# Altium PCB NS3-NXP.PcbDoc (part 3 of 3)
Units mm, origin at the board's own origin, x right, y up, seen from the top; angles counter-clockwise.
Board outline 147 x 83 mm, 2 copper layers (Top Layer, Bottom Layer); 303 components, 312 nets, 1163 pads, 118 vias.
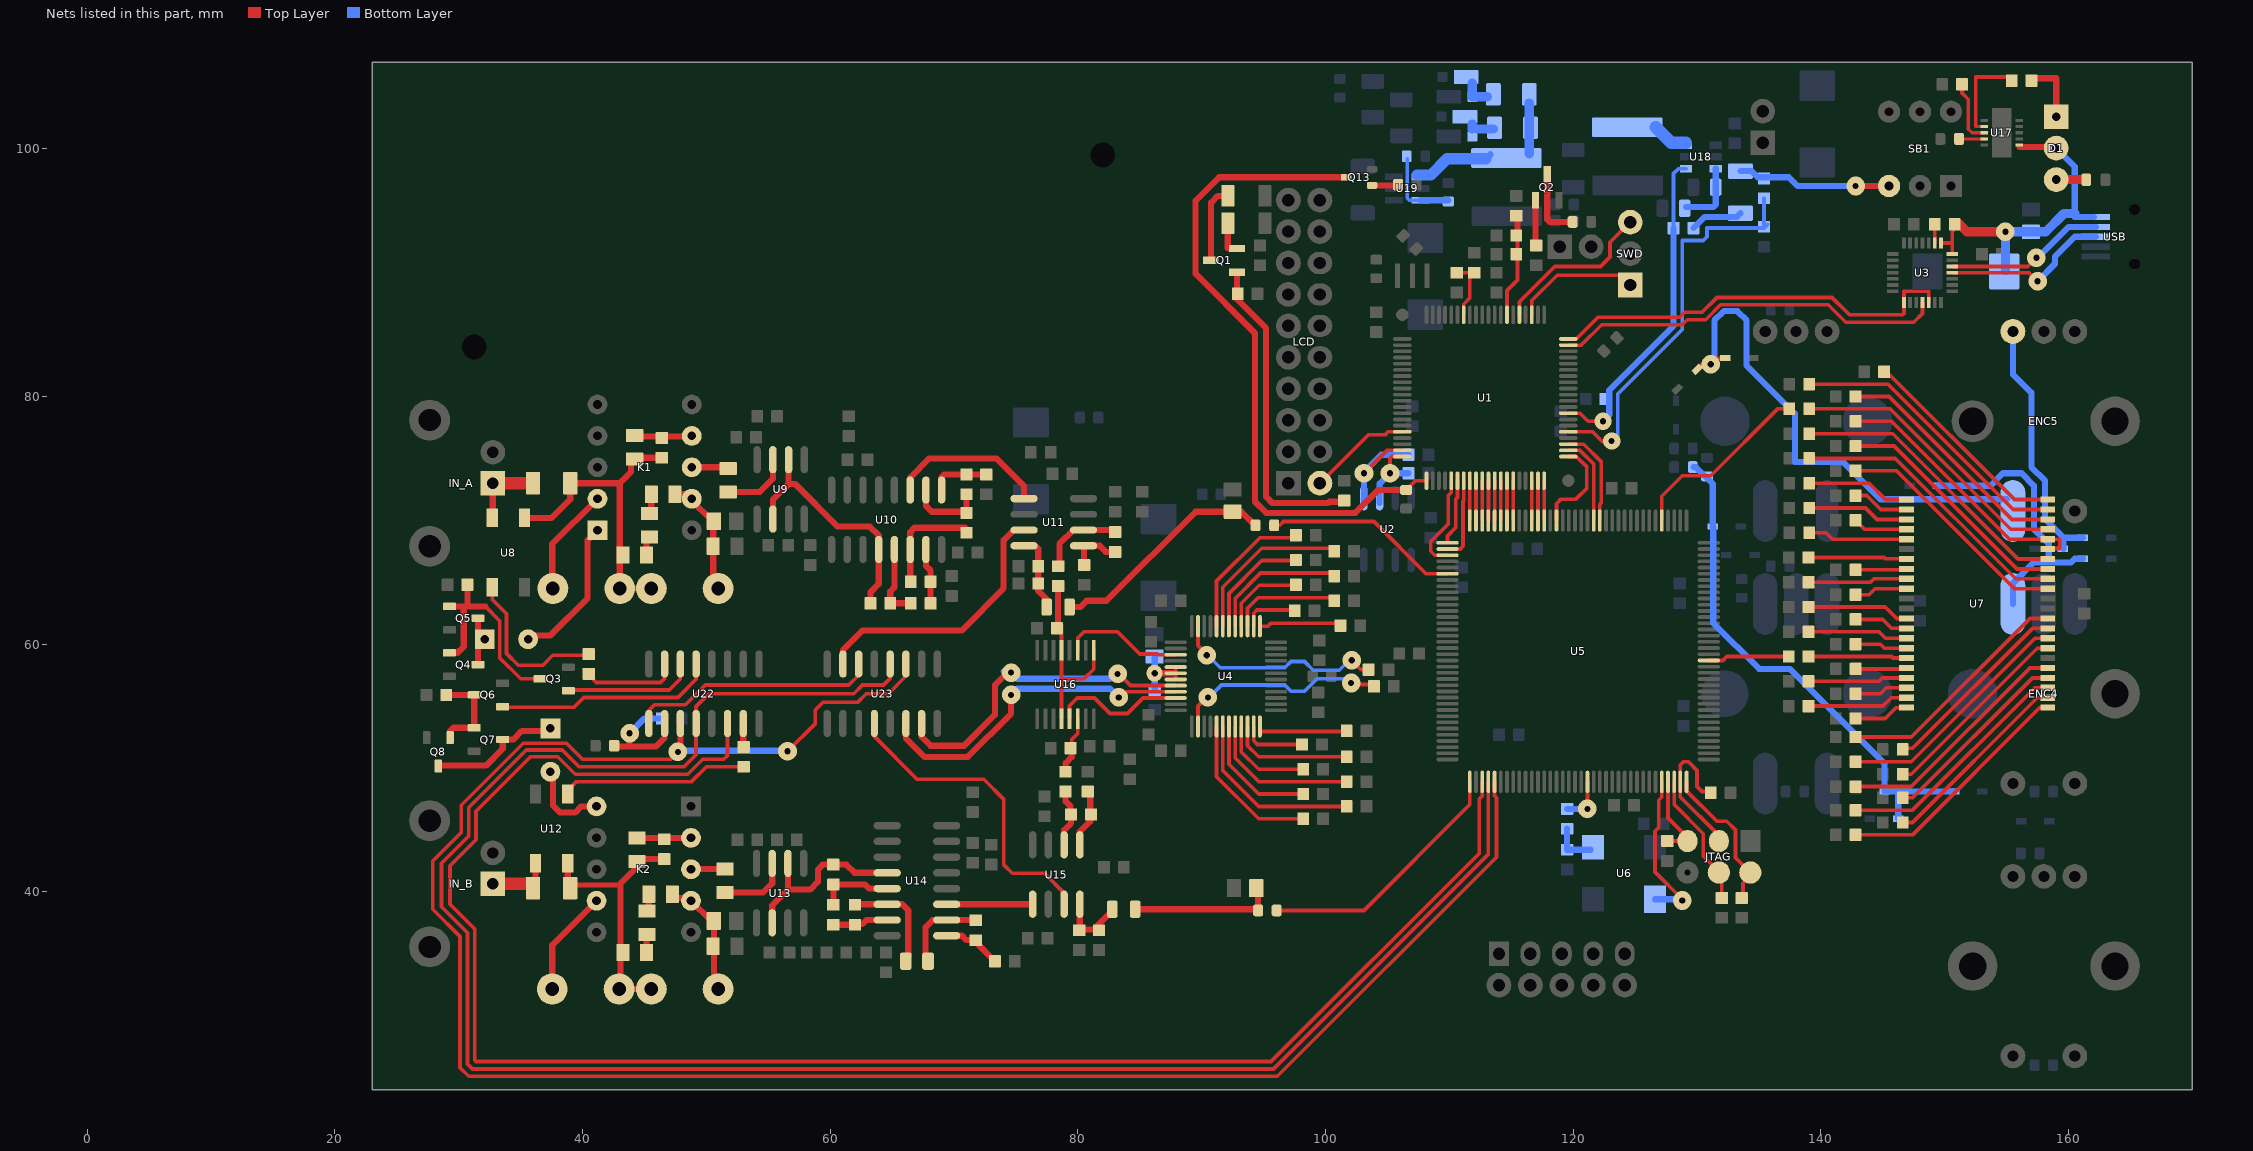
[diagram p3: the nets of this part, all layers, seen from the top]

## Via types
v1: diameter 1.5, hole 0.5, Top Layer to Bottom Layer, 93 vias
v2: diameter 1.6, hole 0.5, Top Layer to Bottom Layer, 18 vias
v3: diameter 1.4, hole 0.5, Top Layer to Bottom Layer, 4 vias
v4: diameter 1.2, hole 0.5, Top Layer to Bottom Layer, 2 vias
v5: diameter 1.3, hole 0.5, Top Layer to Bottom Layer, 1 vias

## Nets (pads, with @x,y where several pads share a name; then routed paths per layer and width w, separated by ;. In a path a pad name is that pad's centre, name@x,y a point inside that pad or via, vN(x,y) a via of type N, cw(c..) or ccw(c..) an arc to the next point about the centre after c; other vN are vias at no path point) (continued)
NetC14_1: C14.1 C15.2 U4.5 U4.6 U4.7 | length 5.4
  Top Layer w0.3: U4.7@87.898,57.154 U4.6@87.898,57.654 U4.5@87.898,58.154
  Top Layer w0.5: v5(86.2,57.65) U4.6@87.894,57.65
  Bottom Layer w0.5: C14.1@86.2,56.3 v5(86.2,57.65) C15.2@86.2,59
NetC40_1: C40.1 IN_A.1 U8.4 | length 6
  Top Layer w0.5: U8.4@32.75,70.25 IN_A.1@32.75,73
  Top Layer w1: IN_A.1@32.75,73 C40.1@36,73
NetC40_2: C40.2 C41.2 C43.1 C44.1 R89.2 R93.1 U8.3 | length 25.5
  Top Layer w0.5: U8.3@35.3,70.2 37.5,70.2 39,71.7 C40.2@39,73 43,73 ; C41.2@45.55,64.5 C43.1@43,64.5 43,73 ; C44.1@46.4,75.05 44.05,75.05 43.9,74.9 43.9,73.9 43,73
NetC41_1: C41.1 C42.2 K1.9 R91.1 R92.2 | length 9.6
  Top Layer w0.5: R91.1@47.45,72.1 48.46,72.1 K1.9@48.82,71.74 ; K1.9@48.75,71.68 50.55,69.88 50.55,64.9 C41.1@50.95,64.5
NetC43_2: C43.2 K1.2 | length 8.7
  Top Layer w0.5: C43.2@37.55,64.5 37.55,68.1 K1.2@41.13,71.68
NetC44_2: C44.2 K1.7 R93.2 | length 4.8
  Top Layer w0.5: R93.2@43.94,76.76 K1.7@48.75,76.76
NetC49_2: C49.2 R103.2 R104.1 U11.4 | length 6.2
  Top Layer w0.5: U11.4@75.65,67.945 76.555,67.945 76.8,67.7 R103.2@76.8,66.3 C49.2@76.8,64.9 76.8,64.3 77.475,63.625 R104.1@77.475,63
NetC50_2: C50.2 R104.2 R105.1 | length 18.6
  Top Layer w0.5: R104.2@79.325,63 80.2,63 80.7,63.5 82.3,63.5 89.5,70.7 C50.2@92.5,70.7 93.2,70.7 R105.1@94.3,69.6
NetC53_2: C53.2 R106.2 U16.1 U16.5 U16.12 | length 15.4
  Top Layer w0.3: C53.2@78.3,61.3 78.3,61.5 C53.2@78.4,61.6 ; U16.12@78.675,53.975 78.675,57.2 ; C53.2@78.675,61.5 U16.5@78.675,59.525 78.675,57.2 ; U16.1@81.275,59.525 81.275,57.975 80.5,57.2 78.675,57.2
  Top Layer w0.5: C53.2@78.4,61.6 R106.2@78.4,64.7
NetC54_1: C54.1 Q4.3 Q5.3 | length 3.6
  Top Layer w0.5: Q4.3@31.55,58.35 Q5.3@31.55,62
NetC54_2: C54.2 K1.1 | length 12.1
  Top Layer w0.5: C54.2@35.6,60.4 35.6,60.5 35.8,60.7 37.4,60.7 40.4,63.7 40.4,68.4 K1.1@41.2,69.2
NetC55_1: C55.1 IN_B.1 U12.3 | length 4.9
  Top Layer w0.5: C55.1@36,40.65 36.2,40.85 U12.3@36.2,42.2
  Top Layer w1: IN_B.1@32.75,40.65 C55.1@36,40.65
NetC55_2: C55.2 C56.2 C58.1 C59.1 R110.2 R113.1 U12.4 | length 21.5
  Top Layer w0.4: C55.2@39.1,40.55 43.05,40.55
  Top Layer w0.5: U12.4@38.8,42.2 38.8,40.85 C55.2@39.1,40.55 ; 43.05,40.55 43.05,32.25 C58.1@42.95,32.15 C56.2@45.55,32.15 ; 43.05,40.65 44.25,41.85 44.25,42.45 44.45,42.65 C59.1@46.6,42.65
NetC56_1: C56.1 C57.2 K2.4 R112.1 R127.2 | length 9.7
  Top Layer w0.5: R112.1@47.35,39.5 48.53,39.5 K2.4@48.75,39.28 50.38,37.65 C57.2@50.6,37.65 50.6,32.5 C56.1@50.95,32.15
NetC58_2: C58.2 K2.7 | length 8.6
  Top Layer w0.5: C58.2@37.55,32.15 37.55,35.7 K2.7@41.13,39.28
NetC59_2: C59.2 K2.2 R113.2 | length 4.5
  Top Layer w0.5: R113.2@44.26,44.36 K2.2@48.75,44.36
NetC64_2: C64.2 R123.2 R124.1 U15.4 | length 5.5
  Top Layer w0.5: U15.4@80.155,39 80.155,36.955 81.645,36.955 81.645,37.345 R124.1@82.775,38.475
NetC65_2: C65.2 R124.2 R125.1 | length 11.7
  Top Layer w0.5: R124.2@84.625,38.6 R125.1@94.45,38.6 ; C65.2@94.4,40.3 94.55,40.15 R125.1@94.55,38.5
NetC68_2: C68.2 R126.2 U16.14 | length 4.7
  Top Layer w0.3: 79.5,50.9 79.5,52.3 79.975,52.775 U16.14@79.975,53.975
  Top Layer w0.5: R126.2@79,49.7 79,50.4 79.5,50.9
NetC69_1: C69.1 Q7.3 Q8.3 | length 10.6
  Top Layer w0.5: Q8.3@28.35,50.2 32.2,50.2 33.55,51.55 Q7.3@33.55,52.3 34.4,52.3 35.1,53 C69.1@37.4,53
NetC69_2: C69.2 K2.10 | length 6.7
  Top Layer w0.5: C69.2@37.4,49.5 37.6,49.3 37.6,47 38.2,46.4 39.4,46.4 39.9,46.9 K2.10@41.13,46.9
  Bottom Layer w0.5: K2.10@41,46.9 K2.10@41.13,46.9
NetC71_2: C71.2 R107.1 U22.10 | length 9.6
  Top Layer w0.5: C71.2@42.609,51.741 43.8,51.741 ; v1(43.8,52.8) 43.8,51.741 ; U22.10@46.625,53.6 46.625,52.425 45.941,51.741 43.8,51.741
  Bottom Layer w0.5: v1(43.8,52.8) 45,54 R107.1@46.4,54
NetC84_2: C84.2 R132.1 R133.2 U1.7 | length 8.3
  Top Layer w0.3: U1.7@114.65,86.6 114.65,88.55 115.5,89.4 C84.2@115.5,93
  Top Layer w0.5: C84.2@115.5,93 R132.1@115.5,94.5
NetC88_1: C88.1 C89.1 L2.2 U19.1 | length 10.7
  Bottom Layer w0.55: L2.2@112.95,99.2 L2.2@113.3,99.55
  Bottom Layer w0.75: L2.2@116.45,99.6 116.45,101.6 C89.1@116.45,103.7
  Bottom Layer w0.9: U19.1@107.4,97.9 108.5,97.9 109.8,99.2 L2.2@112.95,99.2
NetC88_2: C88.2 D18.A D19.C | length 1.7
  Bottom Layer w0.75: 111.85,101.6 111.85,102 ; 112.25,101.6 C88.2@113.55,101.6
NetC89_2: C89.2 D20.A D21.C | length 2.3
  Bottom Layer w0.75: D21.C@111.85,105.3 D20.A@111.85,104.2 C89.2@113.05,104.2
NetC117_1: C117.1 D5.A D7.A D9.A D11.A R151.1 | length 41.9
  Bottom Layer w0.5: R151.1@129.7,74.3 129.9,74.3 131.26,72.94 D7.A@131.26,69.5 ; D7.A@131.3,69.46 131.3,61.7 135,58 137.5,58 145.14,50.36 D9.A@145.14,48.1 D11.A@150.76,48.1 ; D5.A@146.24,45.9 146.24,48.06
NetD1_1: D1.1 R130.2 | length 4.8
  Top Layer w0.5: R130.2@157.3,105.7 159,105.7 D1.1@159,102.6
NetD1_3: D1.3 R129.2 | length 2.4
  Top Layer w0.75: D1.3@159,97.52 R129.2@161.405,97.52
NetD2_A: D2.A R135.2 SB1.3 | length 13.1
  Top Layer w0.5: v1(142.8,97) SB1.3@145.5,97
  Bottom Layer w0.5: D2.A@133.5,98.2 134.4,98.2 134.9,97.7 137.4,97.7 138.1,97 143.1,97 v1@143.1,96.8 ; SB1.3@145.4,97.1 SB1.3@145.5,97
NetD2_C: D2.C R137.1 | length 4.3
  Bottom Layer w0.5: R137.1@129.7,93.6 130.6,94.5 133.2,94.5 D2.C@133.5,94.8
NetD12_C: D12.C D13.C ENC4.1 | length 23.4
  Bottom Layer w0.5: D13.C@149.44,72.8 153.7,72.8 154.7,73.8 156.2,73.8 157.2,72.8 157.2,69.3 158.4,68.1 158.4,66.6 ; ENC4.1@155.5,63.25 155.5,64.9 157.2,66.6 158.4,66.6 ; D12.C@161.16,66.9 160.5,66.9 160.2,66.6 158.4,66.6
NetD14_C: D14.C D15.C ENC5.1 | length 20.8
  Bottom Layer w0.5: ENC5.1@155.5,85.25 155.5,81.8 157,80.3 157,74.3 158.1,73.2 158.1,70.1 159.6,68.6 ; D15.C@159.6,67.7 159.6,68.6 ; D14.C@161.16,68.6 159.6,68.6
NetD16_C: D16.C D17.C ENC5.4 | length 40.9
  Top Layer w0.3: D16.C@130.006,82.206 130.4,82.6 v1(131.1,82.6) 131.6,83.1 D17.C@132.26,83.1
  Bottom Layer w0.5: v1(131.1,82.6) 131.4,82.9 131.4,86.138 132.162,86.9 133.238,86.9 134,86.138 134,82.5 137.9,78.6 137.9,74.7 141.8,74.7 144.8,71.7 ENC5.4@155,71.7
NetK1_8: K1.8 R94.1 | length 2.9
  Top Layer w0.5: K1.8@48.82,74.28 R94.1@51.67,74.28
NetK2_3: K2.3 R114.1 | length 2.7
  Top Layer w0.5: K2.3@48.78,41.85 R114.1@51.5,41.85
NetL1_1: L1.1 U18.3 | length 3
  Bottom Layer w1: L1.1@126.65,101.75 127.9,100.5 U18.3@129.1,100.5
NetQ1_1: Q1.1 R6.1 R7.1 | length 25.7
  Top Layer w0.5: Q1.1@92.85,90.05 92.85,87.85 95.2,85.5 95.2,71.9 95.7,71.4 100.2,71.4 100.3,71.5 R7.1@101.5,71.5
NetQ1_2: Q1.2 R8.2 | length 2.8
  Top Layer w0.5: R8.2@92.1,94 92.1,92 92.15,91.95 Q1.2@92.85,91.95
NetQ1_3: Q1.3 R3.2 | length 6.2
  Top Layer w0.5: Q1.3@90.75,91 90.75,95.65 91.3,96.2 R3.2@92.1,96.2
NetQ2_1: Q2.1 R14.2 | length 3.6
  Top Layer w0.5: R14.2@116.95,92.25 Q2.1@116.95,95.85
NetQ2_3: Q2.3 R15.1 | length 5.8
  Top Layer w0.5: Q2.3@117.9,97.95 117.9,94.3 118.1,94.1 R15.1@119.95,94.1
NetQ3_3: Q3.3 Q4.1 Q5.1 R108.2 | length 17.1
  Top Layer w0.3: 32.15,63.05 33.3,61.9 33.3,58.9 35,57.2 Q3.3@36.6,57.2
  Top Layer w0.5: Q5.1@29.25,63.05 30.4,63.05 ; 29.9,59.3 30.4,59.8 30.4,63.05 ; 30.7,63.15 R108.2@30.7,64.8 ; 32.15,63.05 30.4,63.05
NetQ6_3: Q6.3 Q7.1 Q8.1 R128.2 | length 7.5
  Top Layer w0.5: R128.2@29,55.9 Q6.3@31.25,55.9 Q7.1@31.25,53.25 29.55,53.25 29.3,53 Q8.1@29.3,52.45
NetQ13_1: Q13.1 R2.1 | length 2
  Top Layer w0.5: Q13.1@103.75,97.05 R2.1@105.8,97.05
NetR19_2: R19.2 U3.9 | length 1.5
  Top Layer w0.3: U3.9@149.2,92.4 R19.2@149.2,93.9
NetR20_2: R20.2 U4.47 | length 17.3
  Top Layer w0.3: U4.47@89.698,61.454 89.698,59.902 90.4,59.2 v1(90.4,59.1) ; v1(102.114,58.698) 102.87,57.942 R20.2@103.474,57.942
  Bottom Layer w0.3: v1(90.4,59.1) 90.5,59.1 91.5,58.1 96.7,58.1 97.2,58.6 98.3,58.6 99,57.9 101.1,57.9 101.898,58.698 v1(102.114,58.698)
NetR21_2: R21.2 U4.14 | length 17.4
  Top Layer w0.3: U4.14@89.698,53.354 89.698,54.998 90.5,55.8 v1(90.5,55.7) ; v1@102.061,56.75 R21.2@103.842,56.75
  Bottom Layer w0.3: v1(90.5,55.7) 90.6,55.7 91.6,56.7 96.7,56.7 97.2,56.2 98.3,56.2 99.3,57.2 101.523,57.2 101.762,56.962 101.961,56.962 v1(102.061,56.862)
NetR22_1: R22.1 U4.37 | length 6.6
  Top Layer w0.3: U4.37@94.698,61.454 95.354,61.454 95.6,61.7 100.9,61.7 R22.1@101.1,61.5
NetR23_1: R23.1 U4.38 | length 4.5
  Top Layer w0.3: U4.38@94.198,61.454 94.198,62.498 94.452,62.752 R23.1@97.5,62.752
NetR24_1: R24.1 U4.39 | length 8.9
  Top Layer w0.3: U4.39@93.698,61.454 93.698,62.898 94.55,63.75 100.45,63.75 R24.1@100.7,63.5
NetR25_1: R25.1 U4.40 | length 6.8
  Top Layer w0.3: U4.40@93.198,61.454 93.198,63.298 94.65,64.75 R25.1@97.6,64.75
NetR26_1: R26.1 U4.41 | length 11.2
  Top Layer w0.3: U4.41@92.698,61.454 92.698,63.698 94.75,65.75 100.45,65.75 R26.1@100.7,65.5
NetR27_1: R27.1 U4.42 | length 9.1
  Top Layer w0.3: U4.42@92.198,61.454 92.198,64.098 94.85,66.75 R27.1@97.6,66.75
NetR28_1: R28.1 U4.43 | length 13.6
  Top Layer w0.3: U4.43@91.698,61.454 91.698,64.598 94.85,67.75 100.45,67.75 R28.1@100.7,67.5
NetR29_1: R29.1 U4.44 | length 11.7
  Top Layer w0.3: U4.44@91.198,61.454 91.198,65.098 94.7,68.6 97.55,68.6 R29.1@97.7,68.75
NetR30_1: R30.1 U4.24 | length 7
  Top Layer w0.3: U4.24@94.698,52.954 R30.1@101.7,52.954
NetR31_1: R31.1 U4.23 | length 4.8
  Top Layer w0.3: U4.23@94.198,53.354 94.198,52.202 94.5,51.9 R31.1@97.76,51.9
NetR32_1: R32.1 U4.22 | length 9.9
  Top Layer w0.3: U4.22@93.698,53.354 93.698,51.802 94.6,50.9 R32.1@101.7,50.9
NetR33_1: R33.1 U4.21 | length 7.6
  Top Layer w0.3: U4.21@93.198,53.354 93.198,51.302 94.6,49.9 R33.1@98.2,49.9
NetR34_1: R34.1 U4.20 | length 12.3
  Top Layer w0.3: U4.20@92.698,53.354 92.698,50.802 94.6,48.9 R34.1@101.7,48.9
NetR35_1: R35.1 U4.19 | length 10
  Top Layer w0.3: U4.19@92.198,53.354 92.198,50.302 94.6,47.9 R35.1@98.2,47.9
NetR36_1: R36.1 U4.18 | length 14.8
  Top Layer w0.3: U4.18@91.698,53.354 91.698,49.802 94.6,46.9 R36.1@101.7,46.9
NetR37_1: R37.1 U4.17 | length 12.5
  Top Layer w0.3: U4.17@91.198,53.354 91.198,49.302 94.6,45.9 R37.1@98.2,45.9
NetR38_1: R38.1 R80.1 U6.3 | length 3.6
  Bottom Layer w0.5: R38.1@119.5,45.1 R80.1@119.5,43.4 U6.3@121.4,43.4
NetR38_2: R38.2 U5.20 | length 3.8
  Top Layer w0.3: v1(121.146,46.7) U5.20@121.146,48.886
  Bottom Layer w0.5: R38.2@119.5,46.7 v1(121.146,46.7)
NetR39_2: R39.2 U7.7 | length 8
  Top Layer w0.3: R39.2@139,67 145.1,67 145.2,66.9 146.892,66.9 U7.7@146.916,66.876
NetR40_2: R40.2 U7.8 | length 4
  Top Layer w0.3: R40.2@142.8,66 U7.8@146.84,66
NetR41_2: R41.2 U7.9 | length 8.1
  Top Layer w0.3: R41.2@138.9,65 144,65 144.276,65.276 U7.9@146.916,65.276
NetR42_2: R42.2 U7.10 | length 4.3
  Top Layer w0.3: R42.2@142.8,64 143.9,64 144.376,64.476 U7.10@146.916,64.476
NetR43_2: R43.2 U7.13 | length 8.3
  Top Layer w0.3: R43.2@139,63 145.2,63 146.124,62.076 U7.13@146.916,62.076
NetR44_2: R44.2 U7.14 | length 4.4
  Top Layer w0.3: R44.2@142.8,62 145,62 145.724,61.276 U7.14@146.916,61.276
NetR45_2: R45.2 U7.15 | length 8.1
  Top Layer w0.3: R45.2@139,61 144.7,61 145.224,60.476 U7.15@146.916,60.476
NetR46_2: R46.2 U7.16 | length 4.3
  Top Layer w0.3: R46.2@142.8,60 144.8,60 145.124,59.676 U7.16@146.916,59.676
NetR47_2: R47.2 U7.29 | length 15.9
  Top Layer w0.3: R47.2@146.6,49.5 147.3,49.5 157.476,59.676 U7.29@158.316,59.676
NetR48_2: R48.2 U7.30 | length 19.6
  Top Layer w0.3: R48.2@142.8,50.5 147.3,50.5 157.276,60.476 U7.30@158.316,60.476
NetR49_2: R49.2 U7.31 | length 15.7
  Top Layer w0.3: R49.2@146.6,51.6 147.4,51.6 157.076,61.276 U7.31@158.316,61.276
NetR50_2: R50.2 U7.32 | length 19.5
  Top Layer w0.3: R50.2@142.8,52.5 147.3,52.5 156.876,62.076 U7.32@158.316,62.076
NetR51_2: R51.2 U7.35 | length 19.5
  Top Layer w0.3: R51.2@142.8,74 146.1,74 155.624,64.476 U7.35@158.316,64.476
NetR52_2: R52.2 U7.36 | length 23.3
  Top Layer w0.3: R52.2@139.05,75 146,75 155.724,65.276 U7.36@158.316,65.276
NetR53_2: R53.2 U7.37 | length 19.6
  Top Layer w0.3: R53.2@142.8,76 145.9,76 155.824,66.076 U7.37@158.316,66.076
NetR54_2: R54.2 U7.38 | length 23.5
  Top Layer w0.3: R54.2@139.05,77 145.8,77 155.924,66.876 U7.38@158.316,66.876
NetR55_1: R55.1 U7.1 | length 8.4
  Top Layer w0.3: R55.1@139.05,73 143.9,73 145.224,71.676 U7.1@146.916,71.676
NetR56_1: R56.1 U7.2 | length 4.6
  Top Layer w0.3: R56.1@142.8,72 143.7,72 144.824,70.876 U7.2@146.916,70.876
NetR57_1: R57.1 U7.3 | length 8.2
  Top Layer w0.3: R57.1@139.05,71 143.6,71 144.524,70.076 U7.3@146.916,70.076
NetR58_1: R58.1 U7.4 | length 4.4
  Top Layer w0.3: R58.1@142.8,70 143.524,69.276 U7.4@146.916,69.276
NetR59_1: R59.1 U7.5 | length 8.1
  Top Layer w0.3: R59.1@139.05,69 140.4,69 140.924,68.476 U7.5@146.916,68.476
NetR60_1: R60.1 U7.18 | length 4
  Top Layer w0.3: R60.1@142.8,58 U7.18@146.84,58
NetR61_1: R61.1 U7.19 | length 8
  Top Layer w0.3: R61.1@139,57 144.7,57 144.976,57.276 U7.19@146.916,57.276
NetR62_1: R62.1 U7.20 | length 4.3
  Top Layer w0.3: R62.1@142.8,56 144.8,56 145.276,56.476 U7.20@146.916,56.476
NetR63_1: R63.1 U7.21 | length 8.2
  Top Layer w0.3: R63.1@139,55 145,55 145.676,55.676 U7.21@146.916,55.676
NetR64_1: R64.1 U7.22 | length 4.5
  Top Layer w0.3: R64.1@142.8,54 145.2,54 146.076,54.876 U7.22@146.916,54.876
NetR65_1: R65.1 U7.23 | length 19.8
  Top Layer w0.3: R65.1@142.8,44.6 147.4,44.6 157.676,54.876 U7.23@158.316,54.876
NetR66_1: R66.1 U7.24 | length 15.9
  Top Layer w0.3: R66.1@146.6,45.6 147.4,45.6 157.476,55.676 U7.24@158.316,55.676
NetR67_1: R67.1 U7.25 | length 19.6
  Top Layer w0.3: R67.1@142.8,46.6 147.4,46.6 157.276,56.476 U7.25@158.316,56.476
NetR68_1: R68.1 U7.26 | length 15.7
  Top Layer w0.3: R68.1@146.6,47.6 147.4,47.6 157.076,57.276 U7.26@158.316,57.276
NetR69_1: R69.1 U7.27 | length 19.5
  Top Layer w0.3: R69.1@142.8,48.5 147.3,48.5 156.876,58.076 U7.27@158.316,58.076
NetR70_1: R70.1 U7.42 | length 19.6
  Top Layer w0.3: R70.1@142.8,80 145.5,80 155.424,70.076 U7.42@158.316,70.076
NetR71_1: R71.1 U7.43 | length 23.5
  Top Layer w0.3: R71.1@139.05,81 145.4,81 155.524,70.876 U7.43@158.316,70.876
NetR72_1: R72.1 U7.44 | length 17.5
  Top Layer w0.3: R72.1@145.1,82 145.3,82 155.624,71.676 U7.44@158.316,71.676
NetR73_1: R73.1 U7.17 | length 8
  Top Layer w0.3: R73.1@139,59 145.7,59 145.824,58.876 U7.17@146.916,58.876
NetR74_1: R74.1 U7.41 | length 23.3
  Top Layer w0.3: R74.1@139.05,79 145.6,79 155.324,69.276 U7.41@158.316,69.276
NetR75_1: R75.1 U7.39 U7.40 | length 22.2
  Top Layer w0.3: R75.1@142.8,78 145.7,78 155.224,68.476 U7.40@158.316,68.476 159.276,68.476 159.276,67.724 158.364,67.724 U7.39@158.316,67.676
NetR88_2: R88.2 U8.1 | length 13.2
  Top Layer w0.3: U8.1@32.7,64.6 32.7,63.6 33.85,62.45 33.85,59.25 34.8,58.3 36.8,58.3 37.6,59.1 40.4,59.1 R88.2@40.5,59.2
NetR89_1: R89.1 R90.2 | length 1.2
  Top Layer w0.5: R89.1@45.15,67.2 R90.2@45.15,68.4
NetR90_1: R90.1 R91.2 | length 1.4
  Top Layer w0.5: R90.1@45.55,70.7 R91.2@45.55,72.1
NetR94_2: R94.2 U9.3 | length 5.6
  Top Layer w0.5: R94.2@51.75,72.3 54.3,72.3 55.365,73.365 U9.3@55.365,74.9
NetR95_1: R95.1 R96.2 U10.13 | length 6.1
  Top Layer w0.5: U10.13@65.185,67.65 65.185,64.585 64.85,64.25 R95.1@64.85,63.3 R96.2@66.5,63.3
NetR95_2: R95.2 U9.2 U9.6 U10.12 | length 20.1
  Top Layer w0.5: U9.6@55.365,70.1 55.365,71.665 56.635,72.935 ; U9.2@56.635,74.9 56.635,72.935 ; R95.2@63.25,63.3 63.25,64.2 63.915,64.865 U10.12@63.915,67.65 63.915,68.785 63.2,69.5 60.6,69.5 57.165,72.935 56.635,72.935
NetR96_1: R96.1 R97.2 U10.15 | length 4.5
  Top Layer w0.5: U10.15@67.725,67.65 67.725,66.325 68.1,65.95 R97.2@68.1,65.05 R96.1@68.1,63.3
NetR97_1: R97.1 R98.2 U10.14 | length 8.8
  Top Layer w0.5: R97.1@66.5,65.05 66.455,65.095 U10.14@66.455,67.65 66.455,69.055 66.8,69.4 70.9,69.4 R98.2@71,69.3
NetR98_1: R98.1 R99.2 U10.2 | length 5.9
  Top Layer w0.5: U10.2@67.725,72.45 67.725,71.175 68.2,70.7 R98.1@70.9,70.7 ; R98.1@71,70.8 R99.2@71,72.1
NetR99_1: R99.1 R100.2 U10.1 | length 4.7
  Top Layer w0.5: U10.1@68.995,72.45 68.995,73.495 69.2,73.7 R99.1@71,73.7 R100.2@72.6,73.7
NetR101_2: R101.2 R102.1 U11.5 | length 4.3
  Top Layer w0.5: U11.5@80.45,67.945 81.755,67.945 82.25,67.45 R102.1@83,67.45 ; R101.2@80.5,66.4 U11.5@80.5,67.895
NetR102_2: R102.2 R106.1 U11.6 | length 6.6
  Top Layer w0.5: R106.1@78.5,66.3 78.5,68.1 79.615,69.215 U11.6@80.45,69.215 R102.2@82.835,69.215
NetR105_2: R105.2 U5.114 | length 15.8
  Top Layer w0.3: R105.2@95.9,69.6 96.3,69.6 96.6,69.9 103.9,69.9 108.114,65.686 U5.114@109.846,65.686
NetR109_2: R109.2 U12.1 | length 14.8
  Top Layer w0.3: U12.1@39.1,48.3 39.1,48.5 39.5,48.9 48.8,48.9 50,50.1 R109.2@53,50.1
NetR110_1: R110.1 R111.2 | length 1.4
  Top Layer w0.5: R110.1@45.15,35.1 R111.2@45.15,36.5
NetR111_1: R111.1 R112.2 | length 1.2
  Top Layer w0.5: R111.1@45.35,38.6 R112.2@45.35,39.8
NetR114_2: R114.2 U13.3 | length 5.5
  Top Layer w0.5: R114.2@51.5,39.95 54.38,39.95 ; 54.58,39.95 55.315,40.685 U13.3@55.315,42.3
NetR115_1: R115.1 R116.2 U14.13 | length 6.1
  Top Layer w0.5: R116.2@60.25,38.95 R115.1@60.25,40.6 62.8,40.6 63.135,40.265 U14.13@64.6,40.265
NetR115_2: R115.2 U13.2 U13.6 U14.12 | length 15
  Top Layer w0.5: U13.6@55.315,37.5 55.315,38.915 56.585,40.185 ; U13.2@56.585,42.3 56.585,40.185 ; U14.12@64.6,41.535 61.965,41.535 61.3,42.2 R115.2@60.25,42.2 59.4,42.2 59,41.8 59,40.8 58.385,40.185 56.585,40.185
NetR116_1: R116.1 R117.2 U14.15 | length 4.5
  Top Layer w0.5: R116.1@60.25,37.35 R117.2@62,37.35 62.05,37.4 62.6,37.4 62.925,37.725 U14.15@64.6,37.725
NetR117_1: R117.1 R118.2 U14.14 | length 8.3
  Top Layer w0.5: R117.1@62.045,38.995 U14.14@64.6,38.995 65.805,38.995 66.3,38.5 R118.2@66.3,34.7
NetR118_1: R118.1 R119.2 U14.2 | length 6.9
  Top Layer w0.5: R118.1@67.7,34.5 67.7,37.15 68.275,37.725 U14.2@69.4,37.725 R119.2@71.725,37.725
NetR119_1: R119.1 R120.2 U14.1 | length 4.8
  Top Layer w0.5: U14.1@69.4,36.455 70.645,36.455 71,36.1 R119.1@71.75,36.1 71.75,35.95 R120.2@73.3,34.4
NetR121_2: R121.2 R122.1 U15.5 | length 4.7
  Top Layer w0.5: U15.5@80.155,43.8 80.155,44.845 81,45.69 R121.2@81,48.1
NetR122_2: R122.2 R126.1 U15.6 | length 4.7
  Top Layer w0.5: U15.6@78.885,43.8 78.885,44.985 79.45,45.55 R122.2@79.45,46.25 79.4,46.3 79.4,46.9 79,47.3 R126.1@79,48.1
NetR125_2: R125.2 U5.1 | length 21
  Top Layer w0.3: R125.2@96.05,38.5 103.1,38.5 111.646,47.046 U5.1@111.646,48.886
NetR130_1: R130.1 U17.7 | length 7.4
  Top Layer w0.25: 152.5,105.8 152.5,101.8 U17.7@153.3,101.8
  Top Layer w0.3: 152.5,105.8 R130.1@155.1,105.8
NetR131_2: R131.2 U17.8 | length 5.3
  Top Layer w0.25: 151.9,101.6 152.2,101.3 U17.8@153.3,101.3
  Top Layer w0.3: R131.2@151.4,105.2 151.4,104.5 151.9,104 151.9,101.6
NetR141_1: R141.1 R142.2 U18.6 | length 5.4
  Bottom Layer w0.5: R141.1@129.1,95.3 131.3,95.3 131.5,95.5 U18.6@131.5,98.4
NetR143_1: R143.1 R144.2 U19.3 | length 6.6
  Bottom Layer w0.3: R143.1@106.59,99.2 106.59,96.01 106.75,95.85 U19.3@107.675,95.85
  Bottom Layer w0.5: U19.3@107.675,95.85 R144.2@109.9,95.85
NetRt_2: Rt.2 U17.9 | length 2.1
  Top Layer w0.25: Rt.2@151.15,100.8 U17.9@153.3,100.8
NetSWD_1: SWD.1 U1.3 | length 10.3
  Top Layer w0.3: U1.3@116.65,86.6 116.65,87.75 118.7,89.8 123.8,89.8 SWD.1@124.6,89
NetSWD_3: SWD.3 U1.5 | length 13.4
  Top Layer w0.3: U1.5@115.65,86.6 115.65,87.65 118.5,90.5 122.2,90.5 122.96,91.26 122.96,92.46 SWD.3@124.6,94.1
NetU3_4: U3.4 USB.3 | length 13.7
  Top Layer w0.3: U3.4@150.6,90 156.8,90 v1(157.5,89.3)
  Bottom Layer w0.5: v1(157.5,89.3) 158.9,90.7 158.9,91.3 160.5,92.9 USB.3@162.2,92.9
NetU3_5: U3.5 USB.2 | length 12.9
  Top Layer w0.3: U3.5@150.6,90.5 156.7,90.5 v1(157.4,91.2)
  Bottom Layer w0.5: v1(157.4,91.2) 157.5,91.2 160,93.7 USB.2@162.2,93.7
NetU4_3: U4.3 U16.3 | length 9.9
  Top Layer w0.3: U16.3@79.975,59.525 79.975,60.475 80.5,61 83.2,61 85,59.2 86.4,59.2 86.446,59.154 U4.3@87.898,59.154
NetU4_10: U4.10 U16.13 | length 10.9
  Top Layer w0.3: U16.13@79.325,53.975 79.325,55.025 79.954,55.654 81.346,55.654 82.6,54.4 84,54.4 85.254,55.654 U4.10@87.898,55.654
NetU10_3: U10.3 U11.1 | length 12.8
  Top Layer w0.5: U10.3@66.455,72.45 66.455,73.455 68,75 73.4,75 75.65,72.75 U11.1@75.65,71.755
NetU14_3: U14.3 U15.1 | length 6.9
  Top Layer w0.5: U14.3@69.4,38.995 U15.1@76.34,38.995
NetU22_9: U22.9 U23.14 | length 20.1
  Top Layer w0.3: U22.9@45.355,53.6 45.355,54.655 45.8,55.1 48.3,55.1 49.9,56.7 61.5,56.7 62.295,57.495 U23.14@62.295,58.4
OCA: R88.1 U22.7 | length 7.8
  Top Layer w0.3: R88.1@40.5,57.6 40.5,57.5 41.1,56.9 46.3,56.9 46.625,57.225 U22.7@46.625,58.4
OCB: R109.1 U22.15 | length 1.9
  Top Layer w0.5: R109.1@52.975,51.725 U22.15@52.975,53.6
OE_S-: R74.2 U5.77 | length 15.2
  Top Layer w0.3: U5.77@127.146,69.986 127.146,71.946 128.8,73.6 131.1,73.6 136.5,79 R74.2@137.45,79
ON_A: R137.2 R138.1 U1.68 U18.1 | length 26.6
  Top Layer w0.3: U1.68@119.6,78.65 120.55,78.65 121.2,78 v3(122.4,78)
  Bottom Layer w0.3: R137.2@128.1,93.6 128.1,98 128.5,98.4 U18.1@129.1,98.4
  Bottom Layer w0.5: v3(122.4,78) 122.9,78.5 122.9,80.5 128.1,85.7 R137.2@128.1,93.6
ON_B: R135.1 R136.1 U1.65 | length 32.6
  Top Layer w0.3: U1.65@119.6,77.15 121.55,77.15 122.339,76.361 v3@123.165,76.361
  Bottom Layer w0.3: v3@123.165,76.361 123.6,76.796 123.6,80.2 128.8,85.4 128.8,92.6 130.5,92.6 130.8,92.9 130.8,93.6 135.4,93.6 R136.1@135.7,93.9 ; R136.1@135.4,93.7 R135.1@135.4,96
  other v3: 123.1,76.4
OSCEN: U5.32 U6.1 | length 12.8
  Top Layer w0.3: U5.32@127.146,48.886 127.146,47.646 126.9,47.4 126.9,45.2 126.6,44.9 126.6,41.6 128.8,39.4 v1(128.8,39.3)
  Bottom Layer w0.5: U6.1@126.6,39.4 v1@128.7,39.4
PDN_A-: U11.3 U23.15 | length 22
  Top Layer w0.5: U23.15@61.025,58.4 61.025,59.525 62.6,61.1 70.6,61.1 74,64.5 74,68.4 74.815,69.215 U11.3@75.65,69.215
PDN_B-: U15.3 U23.4 | length 25.6
  Top Layer w0.3: U23.4@63.565,53.6 63.565,52.535 67,49.1 72.4,49.1 74,47.5 74,42.2 74.7,41.5 77.3,41.5 78.885,39.915 U15.3@78.885,39
PWMA: U1.60 U5.96 | length 3.2
  Top Layer w0.3: U5.96@117.646,69.986 U1.60@117.646,73.196
PWMB: U1.59 U5.97 | length 3.2
  Top Layer w0.3: U5.97@117.15,69.99 U1.59@117.15,73.2
Q0: U1.58 U5.98 | length 3.2
  Top Layer w0.3: U5.98@116.65,69.99 U1.58@116.65,73.2
Q1: U1.55 U5.101 | length 3.2
  Top Layer w0.3: U5.101@115.15,69.99 U1.55@115.15,73.2
Q2: U1.54 U5.102 | length 3.2
  Top Layer w0.3: U5.102@114.65,69.99 U1.54@114.65,73.2
Q3: U1.53 U5.103 | length 3.2
  Top Layer w0.3: U5.103@114.15,69.99 U1.53@114.15,73.2
Q4: U1.52 U5.104 | length 3.2
  Top Layer w0.3: U5.104@113.65,69.99 U1.52@113.65,73.2
Q5: U1.51 U5.105 | length 3.2
  Top Layer w0.3: U5.105@113.15,69.986 U1.51@113.15,73.2
Q6: U1.50 U5.106 | length 3.2
  Top Layer w0.3: U5.106@112.646,69.986 112.646,70.943 112.65,70.947 U1.50@112.65,73.2
Q7: U1.49 U5.107 | length 3.2
  Top Layer w0.3: U5.107@112.15,69.99 U1.49@112.15,73.2
RD: U1.48 U5.108 | length 3.2
  Top Layer w0.3: U5.108@111.646,69.986 111.646,70.943 111.65,70.947 U1.48@111.65,73.2
RESET: C2.1 R12.1 U1.14 | length 4.7
  Top Layer w0.3: R12.1@110.6,90 111.65,90 111.65,87.95 111.15,87.45 U1.14@111.15,86.6
RL_CA: Q3.1 U22.6 | length 10.6
  Top Layer w0.3: Q3.1@38.9,56.3 47,56.3 47.895,57.195 U22.6@47.895,58.4
RL_CB: Q6.1 U22.5 | length 17.7
  Top Layer w0.3: Q6.1@33.6,54.9 39.3,54.9 40.1,55.7 47.7,55.7 49.165,57.165 U22.5@49.165,58.4
RS: U1.46 U5.109 | length 5.3
  Top Layer w0.3: U5.109@109.846,68.186 109.846,68.746 110.5,69.4 110.5,71.7 110.65,71.85 U1.46@110.65,73.2
S1: U4.8 U23.7 | length 27.2
  Top Layer w0.3: v1@83.1,57.7 83.2,57.7 84.246,56.654 U4.8@87.898,56.654
  Top Layer w0.5: U23.7@67.375,53.6 67.375,52.525 68.1,51.8 70.8,51.8 73.3,54.3 73.3,56.7 74.4,57.8 v1@74.6,57.8
  Bottom Layer w0.5: v1@74,57.8 v1@74.6,57.8 ; v1(74.6,57.7) 75.1,57.2 82.6,57.2 v1@83.1,57.7
  other v1: 83.2,57.6
S2: U4.9 U23.6 | length 26.7
  Top Layer w0.3: v1@83.7,56 83.854,56.154 U4.9@87.898,56.154
  Top Layer w0.5: U23.6@66.105,53.6 66.105,52.395 67.6,50.9 71.1,50.9 74.6,54.4 v1(74.6,55.9)
  Bottom Layer w0.5: v1(74.6,55.9) 75.1,56.4 82.6,56.4 v1(83.3,55.7)
SCL: R9.1 U1.40 U2.6 | length 6.5
  Top Layer w0.3: v1(105.2,73.8) 105.2,75 105.35,75.15 U1.40@106.2,75.15
  Bottom Layer w0.5: U2.6@104.365,71.4 104.365,72.965 v1(105.2,73.8) R9.1@106.7,73.8
SDA: R10.1 U1.39 U2.5 | length 10.5
  Top Layer w0.3: v1(103.1,73.8) 104.95,75.65 U1.39@106.2,75.65
  Bottom Layer w0.5: U2.5@103.095,71.4 v1@103.095,73.795 ; v1(103.1,73.8) 103.1,73.9 104.5,75.3 R10.1@106.7,75.3
SPI_CS: U1.62 U5.88 | length 7.1
  Top Layer w0.3: U1.62@119.6,75.65 120.55,75.65 121.656,74.544 121.656,72.156 ; U5.88@121.646,69.986 121.646,72.146
SPI_MOSI: U1.61 U5.94 | length 7.9
  Top Layer w0.3: U5.94@118.646,69.986 118.646,71.346 119.012,71.712 120.212,71.712 121.1,72.6 121.1,74.3 120.25,75.15 U1.61@119.6,75.15
SPI_SCK: U1.63 U5.87 | length 8
  Top Layer w0.3: U1.63@119.6,76.15 120.85,76.15 122.25,74.75 122.25,71.404 122.146,71.3 U5.87@122.146,69.986
SPICS: U5.4 U22.12 U23.12 | length 161
  Top Layer w0.3: U23.12@64.835,58.4 64.835,57.235 64.3,56.7 62.6,56.7 61.9,56 50.2,56 49.165,54.965 U22.12@49.165,53.6 49.165,51.065 48.2,50.1 39.7,50.1 38.35,51.45 35.45,51.45 30.8,46.8 30.8,44.5 28.6,42.3 28.6,38.8 30.7,36.7 30.7,26.1 31.1,25.7 95.8,25.7 113.146,43.046 U5.4@113.146,48.886
SPIMOSI: U5.3 U22.14 | length 141.7
  Top Layer w0.3: U22.14@51.705,53.6 51.705,51.005 51.4,50.7 49.7,50.7 48.5,49.5 39.4,49.5 38,50.9 35.8,50.9 31.4,46.5 31.4,44.2 29.3,42.1 29.3,39 31.3,37 31.3,26.4 31.4,26.3 95.6,26.3 112.4,43.1 112.4,47.5 112.646,47.746 U5.3@112.646,48.886
SPISCK: U5.5 U22.11 U23.11 | length 165.8
  Top Layer w0.3: v1(47.7,51.3) 47.1,50.7 40,50.7 38.7,52 35.2,52 30.2,47 30.2,44.8 27.9,42.5 27.9,38.6 30.1,36.4 30.1,25.8 30.8,25.1 96.1,25.1 113.8,42.8 113.8,47.6 113.646,47.754 U5.5@113.646,48.886 ; v1(56.55,51.35) 58.8,53.6 58.8,54.7 59.4,55.3 62.2,55.3 62.9,56 64.7,56 66.105,57.405 U23.11@66.105,58.4
  Top Layer w0.5: v1@47.895,51.695 U22.11@47.895,53.6
  Bottom Layer w0.5: v1@47.4,51.2 47.6,51.4 56.5,51.4 v1(56.55,51.35)
TCK: JTAG.3 R78.2 U5.35 | length 11.9
  Top Layer w0.3: R78.2@131.2,48.1 130.4,48.1 130,48.5 130,49.8 129.3,50.5 128.9,50.5 128.646,50.246 U5.35@128.646,48.886 128.646,47.654 131.76,44.54 JTAG.3@131.76,44.1
TDI: JTAG.4 R77.2 U5.34 | length 11
  Top Layer w0.3: U5.34@128.146,48.886 128.146,47.054 130.5,44.7 130.5,42.9 131.76,41.64 JTAG.4@131.76,41.56 132,41.32 R77.2@132,39.5
TDO: JTAG.2 R79.2 U5.36 | length 12.3
  Top Layer w0.3: U5.36@129.146,48.886 129.146,48.154 131.6,45.7 132.4,45.7 133.1,45 133.1,42.76 JTAG.2@134.3,41.56 134.3,41.3 133.7,40.7 133.7,39.75 R79.2@133.95,39.5
TMS: JTAG.5 R76.2 U5.33 | length 7.2
  Top Layer w0.3: R76.2@127.5,44.1 JTAG.5@129.22,44.1 129.22,44.38 127.646,45.954 U5.33@127.646,48.886
U_RX: U1.80 U3.22 U3.26 | length 33.8
  Top Layer w0.3: U1.80@119.6,84.65 120.25,84.65 122,86.4 128.6,86.4 129,86.8 130.4,86.8 131.6,88 140.9,88 142.3,86.6 146.6,86.6 146.7,86.7 U3.22@146.7,87.6 146.7,88.5 148.7,88.5 U3.26@148.7,87.6
U_TX: U1.79 U3.25 | length 31.7
  Top Layer w0.3: U1.79@119.6,84.15 120.65,84.15 122.3,85.8 128.8,85.8 129.2,86.2 130.7,86.2 131.9,87.4 140.6,87.4 142,86 147.5,86 148.2,86.7 U3.25@148.2,87.6
UART_HA: Q13.3 R1.1 U1.41 | length 54.5
  Top Layer w0.3: R1.1@106.5,72.45 107.25,73.2 U1.41@108.15,73.2
  Top Layer w0.5: Q13.3@101.65,97.7 91.4,97.7 89.5,95.8 89.5,89.9 94.3,85.1 94.3,71.5 95.2,70.6 102.4,70.6 104.25,72.45 R1.1@106.5,72.45
VUSB: C11.A C80.2 D1.2 R19.1 U3.7 U3.8 U17.1 USB.1 | length 27.8
  Top Layer w0.3: U3.8@149.7,92.4 150.6,92.4 ; U3.7@150.6,91.5 150.6,92.4 ; R19.1@150.8,93.9 150.8,93.5 150.6,93.3 150.6,92.4
  Top Layer w0.5: 156.05,100.15 158.91,100.15 D1.2@159,100.06
  Top Layer w0.75: R19.1@150.8,93.9 151.2,93.9 151.8,93.3 v1(154.9,93.3)
  Bottom Layer w0.5: D1.2@159,100.06 160.5,98.56 160.5,94.77 160.5,94.5 USB.1@162.045,94.5
  Bottom Layer w0.75: C11.A@154.9,90.2 v1(154.9,93.3) 158.154,93.3 159.624,94.77 160.5,94.77
WE_S-: R73.2 U5.53 | length 6.6
  Top Layer w0.3: U5.53@130.946,58.686 132.086,58.686 132.4,59 R73.2@137.4,59
WR: U1.47 U5.110 | length 6.7
  Top Layer w0.3: U5.110@109.846,67.686 110.886,67.686 111.1,67.9 111.1,71.55 111.15,71.6 U1.47@111.15,73.2
WR_573: LCD.2 U1.36 | length 8.4
  Top Layer w0.3: LCD.2@99.54,73 103.44,76.9 104.8,76.9 105.05,77.15 U1.36@106.2,77.15
WR_SRAM_RDY: U1.45 U5.111 | length 7.9
  Top Layer w0.3: U5.111@109.846,67.186 108.814,67.186 108.5,67.5 108.5,68.3 109.9,69.7 109.9,72 110.15,72.25 U1.45@110.15,73.2
pads on no net: K1.4 K1.5 K1.6 K2.5 K2.6 K2.9 SB1.1 SB1.4 SB1.5 SB1.6 U1.1 U1.2 U1.4 U1.11 U1.13 U1.15 U1.37 U1.44 U1.81 U1.82 U2.7 U3.1 U3.2 U3.10 U3.12 U3.13 U3.14 U3.15 U3.16 U3.17 U3.18 U3.19 U3.20 U3.21 U3.23 U3.24 U3.27 U3.28 U4.25 U4.26 U4.35 U4.36 U5.2 U5.6 U5.18 U5.21 U5.22 U5.23 U5.24 U5.27 U5.28 U5.29 U5.30 U5.31 U5.81 U5.84 U5.85 U5.86 U5.89 U5.91 U5.93 U5.95 U5.112 U5.113 U5.117 U5.127 U5.129 U5.131 U5.133 U5.134 U7.28 U9.1 U9.5 U9.8 U13.1 U13.5 U13.8 U17.2 U17.6 U18.5 U19.6 U22.4 U23.9 USB.0 USB.4

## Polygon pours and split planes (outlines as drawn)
VUSB on Top Layer "Bottom Layer-No Net" (solid, pour order 21): 155.7,100.4 155.7,99.9 156.8,99.9 156.8,100.4
BATT on Top Layer "Bottom Layer-No Net" (solid, pour order 19): 153.5,100.45 153.5,99.9 152.2,99.9 152.2,100.45
DGND on Top Layer "Bottom Layer-No Net" (solid, remove dead copper, pour order 7): 94.698,60.154 92,60.154 92,54.654 94.698,54.654
AGND on Top Layer "Bottom Layer-No Net" (solid, remove dead copper, pour order 10): 95,24 95,107 23,107 23,24
DGND on Top Layer "Bottom Layer-No Net" (solid, remove dead copper, pour order 9): 170,107 170,24 95.5,24 95.5,107
VUSB on Bottom Layer "Bottom Layer-No Net" (solid, remove dead copper, pour order 8): 163.35,94.284 163.35,95.742 160.326,95.742 160.326,94.284
AGND on Bottom Layer "Bottom Layer-No Net" (solid, remove dead copper, pour order 11): 23,24 95,24 95,70.5 93.5,72 93.5,97 95,98.5 95,107 23,107
DGND on Bottom Layer "Bottom Layer-No Net" (solid, remove dead copper, pour order 12): 170,24 170,107 95.5,107 95.5,94 94.5,93 94.5,72.5 95.5,71.5 95.5,69.2 95,69.2 95,58.6 95.5,58.6 95.5,56.2 95,56.2 95,45.5 95.5,45.5 95.5,24

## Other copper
Top Layer:
  pour cut-out: 42.5,78 50,78 50,75.5 53.2,75.5 53.2,75.9 58.47,75.934 58.5,71 50.5,71 50.5,62 36,62 36,68.6 31.1,68.6 31.1,74.5 39.5,74.5 39.5,72.5 42.5,72.5
  pour cut-out: 42.6,44.9 43.2,45.5 50,45.5 50,42.506 54.045,42.5 54,38.5 50.3,38.5 50.3,29.8 36,29.8 36,39 31.2,39 31.2,42.2 35.1,42.2 35.1,43.5 39.8,43.5 39.8,37.9 42.5,37.9
  pour cut-out: 54.045,43 54,42.955 54,36.5 60,36.5 60,43
  pour cut-out: 143.5,64.5 144,65 147,65 146.996,64.996 146.996,62.42 143.58,62.42 143.5,62.5
  pour cut-out: 104.6,97.1 104.6,98.9 101.7,98.9 101.7,97.1
  text "Neil Scope-3 NXP" at 37.2,102.4 h5
  text "Rev. 1.1" at 50,98.5 h3
Bottom Layer:
  pour cut-out: 123.1,36.5 123.1,31 112.5,31 112.5,36.5
  text "Neil Scope-3 NXP" at 72.75,102.4 h5
  text "Rev. 1.1" at 59.3,98.5 h3

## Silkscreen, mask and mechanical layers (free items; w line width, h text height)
Top Solder:
  rectangle: 145.7,87.5 150.7,92.5
OutBoard:
  the board outline again, w0.254
Text base:
  rectangle: 126,22.5 164.5,111.5
  rectangle: 26.2,22.5 126,42
  rectangle: 26.2,42 36,111.5
  rectangle: 36,98.55 126.05,111.5
Text:
  circle w1: c158.3,78 r4.5
  circle w1: c158,56 r4.5
  circle w1: c138,56 r4.5
  circle w1: c138,78 r4.5
  circle w1: c158.2,34 r4.5
  circle w1: c148,100 r4
  circle w0.5: c158.999,99.5 r1.501
  lines w0.254: 26.4,34 35.7,34 35.7,41.9 ; 26.4,47.5 35.6,47.5 ; 26.4,66 35.6,66 ; 26.4,80 35.6,80 ; 128,47.5 ccw(c129.5,47.5) 129.5,46 146.5,46 ccw(c146.5,47.5) 148,47.5 148,64.5 ccw(c146.5,64.5) 146.5,66 129.5,66 ccw(c129.5,64.5) 128,64.5 128,47.5 ; 128,69.5 ccw(c129.5,69.5) 129.5,68 146.5,68 ccw(c146.5,69.5) 148,69.5 148,86.5 ccw(c146.5,86.5) 146.5,88 129.5,88 ccw(c129.5,86.5) 128,86.5 128,69.5
  lines w0.5: 26.2,22.6 26.2,111.3 164.5,111.3 164.5,22.6 ; 35.8,41.7 126.05,41.7 126.05,98.55 35.8,98.55 35.8,41.7
  lines w0.54: 26.2,22.6 164.5,22.6
  lines w1: 110.5,30.4 128.5,30.4 128.5,37 126,37 126,38.5 113,38.5 113,37 110.5,37 110.5,30.4
  text "PWR" at 153,105.2 h5
  text "NEIL SCOPE-3" at 107.2,102.1 h10
  text "CH A" at 143.3,83.7 h5
  text "Level" at 163.4,83.7 h5
  text "CH" at 34.5,75 h6
  text "A" at 33.5,67 h8
  text "CH B" at 143.3,61.7 h5
  text "T/Div" at 163.3,61.7 h5
  text "CH" at 34.6,42.7 h6
  text "Menu" at 163.5,39.7 h5
  text "B" at 33.1,35 h8
  text "GND" at 135.6,34.2 h3
  text "D6...D0" at 108.7,34.1 h3
  text "D7...D1" at 108.7,31.6 h3
  text "GND" at 135.6,31.6 h3
  text "Dig. Inp." at 127.5,25.8 h5
CHA:
  circle w1: c146.5,86.5 r1
  circle w1: c129.5,86.5 r1
  circle w1: c129.5,69.5 r1
  circle w1: c146.5,69.5 r1
  rectangle: 26.4,66 35.7,80
  region: 148,86.5 146.5,88 129.5,88 128,86.5 128,69.5 129.5,68 146.5,68 148,69.5
CHB:
  circle w1: c146.5,64.5 r1
  circle w1: c129.5,64.5 r1
  circle w1: c129.5,47.5 r1
  circle w1: c146.5,47.5 r1
  rectangle: 26.4,34 35.7,47.5
  region: 148,64.5 146.5,66 129.5,66 128,64.5 128,47.5 129.5,46 146.5,46 148,47.5
LCD:
  lines w0.254: 33.5,40.75 131,40.75 131,98.25 33.5,98.25 33.5,40.75 ; 36.5,43.75 123,43.75 123,95.25 36.5,95.25 36.5,43.75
